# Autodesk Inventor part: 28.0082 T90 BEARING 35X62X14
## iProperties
Created: 2006-02
Part Number: 28.0082 T90 BEARING 35X62X14
Material: Steel, Mild
Description: Rolling bearings: ball bearings cylindrical and spherical roller bearings- Specification for dimensions of ball bearings, cylindrical and spherical roller beari
Document SubType Name: Modeling
Standard: BS 292: Part 1
Designer: Andy Moles
Standards Organization: BSI
Language: en-US
Size Designation: 7007 - 35 x 62 x 14
Categories: <MemberInstance><Categories><Category DisplayName="Shaft Parts" InternalName="7f7aeb1f-a693-4053-b835-cee3144e0d98" Mnemonic="SHFT"><Category DisplayName="Beari
Density: 1 g/cm^3
Author: Andy Moles
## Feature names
1. Body [Revolution]
2. Fillet1
3. Ball [Revolution]
4. Balls [Circular Pattern]
